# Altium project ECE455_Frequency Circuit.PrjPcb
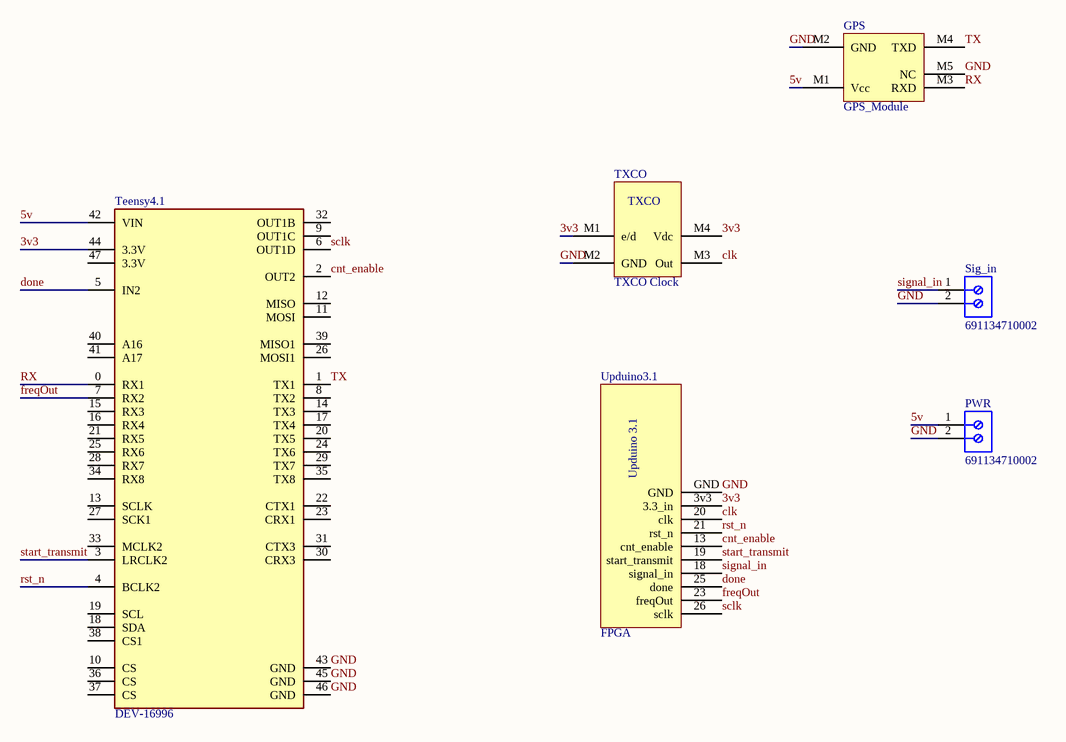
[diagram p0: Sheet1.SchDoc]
1 sheet, 6 parts. Net scope: global (net labels, ports and power ports of the same name join across sheets).
Board file: PCB1.PcbDoc

## Sheet Sheet1.SchDoc
size A; SheetNumber: 1; SheetTotal: 1

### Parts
GPS  GPS_Module  [GPS]
PWR  691134710002  [691134710002]
Sig_in  691134710002  [691134710002]
Teensy4.1  DEV-16996  [FP-DEV-16996-MFG]
TXCO  TXCO Clock  [TXCO Clock]
Upduino3.1  FPGA  [UPduinov3.1]

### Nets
3v3: Teensy4.1.44(3.3V) TXCO.M1(e/d) TXCO.M4(Vdc) Upduino3.1.3v3(3.3_in)
5v: GPS.M1(Vcc) PWR.1 Teensy4.1.42(VIN)
clk: TXCO.M3(Out) Upduino3.1.20(clk)
cnt_enable: Teensy4.1.2(OUT2) Upduino3.1.13(cnt_enable)
done: Teensy4.1.5(IN2) Upduino3.1.25(done)
freqOut: Teensy4.1.7(RX2) Upduino3.1.23(freqOut)
GND: GPS.M2(GND) GPS.M5(NC) PWR.2 Sig_in.2 Teensy4.1.43(GND) Teensy4.1.45(GND) Teensy4.1.46(GND) TXCO.M2(GND) Upduino3.1.GND
rst_n: Teensy4.1.4(BCLK2) Upduino3.1.21(rst_n)
RX: GPS.M3(RXD) Teensy4.1.0(RX1)
sclk: Teensy4.1.6(OUT1D) Upduino3.1.26(sclk)
signal_in: Sig_in.1 Upduino3.1.18(signal_in)
start_transmit: Teensy4.1.3(LRCLK2) Upduino3.1.19(start_transmit)
TX: GPS.M4(TXD) Teensy4.1.1(TX1)

Not connected (* = marked no-connect by the designer): Teensy4.1 8(TX2) 9(OUT1C) 10(CS) 11(MOSI) 12(MISO) 13(SCLK) 14(TX3) 15(RX3) 16(RX4) 17(TX4) 18(SDA) 19(SCL) 20(TX5) 21(RX5) 22(CTX1) 23(CRX1) 24(TX6) 25(RX6) 26(MOSI1) 27(SCK1) 28(RX7) 29(TX7) 30(CRX3) 31(CTX3) 32(OUT1B) 33(MCLK2) 34(RX8) 35(TX8) 36(CS) 37(CS) 38(CS1) 39(MISO1) 40(A16) 41(A17) 47(3.3V)

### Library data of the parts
PWR Sig_in = CMP-1502-03295-3: Wire-To-Board Terminal Block, 5mm Pitch, Horizontal, Screw, 2 Poles
Teensy4.1 = CMP-157412-000001-1: TEENSY 4.1 (HEADERS)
